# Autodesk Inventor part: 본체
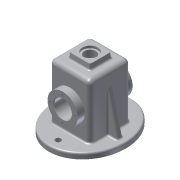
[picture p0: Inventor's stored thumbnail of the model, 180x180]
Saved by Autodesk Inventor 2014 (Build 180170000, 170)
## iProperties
Created: 2017-07
Part Number: 본체
Material: 알루미늄 6061
Document SubType Name: Modeling
Designer: user
Density: 2.71 g/cm^3
Appearance: 알루미늄 - 평지
Mass: 880.579 g
Surface Area: 992.163 cm^2
Volume: 324.937 cm^3
Author: user
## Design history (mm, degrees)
sketch "스케치1" dims "d0" = 75, "d1" = 65
  geometry: L1 (-99.161, 0)-(101.548, 0); C1 r 5 at (-58, 0); C2 r 5 at (58, 0); 2 further points; 1 other entity
  constraints: 3 point on line, 2 centre point, 2 end point, 1 coincident, 1 horizontal, 2 other
  dimensions: "d2" = 10 diameter of C1; "d3" = 10 diameter of C2; "d4" = 58 distance of point (0, 0) C2.centre; "d5" = 58 distance of point (0, 0) C1.centre
extrude "돌출1" new body sketch "스케치1" distance "d6" = 10; taper "d7" = 0 deg
sketch "스케치2"
  geometry: L1 (37, -37)-(-37, -37); L2 (-37, -37)-(-37, 37); L3 (-37, 37)-(37, 37); L4 (37, 37)-(37, -37); L5 (37, -37)-(-37, 37); L6 (-37, -37)-(37, 37); 1 further point
  constraints: 12 end point, 2 midpoint, 2 parallel, 1 horizontal, 1 perpendicular
  dimensions: "d8" = 74 distance of L2.end L3.end; "d9" = 74 distance of L1.end L2.end
extrude "돌출2" join sketch "스케치2" distance "d10" = 100; taper "d11" = 0 deg
sketch "스케치3"
  geometry: L1 (37, 10)-(-37, 10) reference; L2 (37, 10)-(37, 110) reference; L3 (-37, 110)-(37, 110) reference; L4 (-37, 10)-(-37, 110) reference; L5 (32, 105)-(32, 15); L6 (-32, 15)-(-32, 105); L7 (-32, 105)-(32, 105); L8 (32, 15)-(32, 0); L9 (-32, 15)-(-32, 0); L10 (-32, 0)-(32, 0); 1 further point
  constraints: 12 end point, 2 perpendicular, 1 parallel, 1 other
  dimensions: "d12" = 5 distance between parallel lines of L4 L6
extrude "돌출3" cut sketch "스케치3" stored distance "d13" = 64; taper "d14" = 0 deg
sketch "스케치6"
  geometry: L1 (0, 74)-(100, 74) reference; L2 (100, 74)-(100, 0) reference; L3 (-10, 102)-(-10, -28) reference; C1 r 27.5 at (45, 37); C2 r 16 at (45, 37); 1 further point
  constraints: 2 centre point, 1 coincident
  dimensions: "d25" = 55 diameter of C1; "d26" = 32 diameter of C2; "d27" = 37 distance from line of L1 C2.centre; "d29" = 55 distance from line of L3 C1.centre
extrude "돌출5" join sketch "스케치6" distance "d30" = 13; taper "d31" = 0 deg
sketch "스케치7"
  geometry: L1 (37, 10)-(37, 110) reference; L2 (65, 10)-(-65, 10) reference; L3 (65, 10)-(-65, 10) reference; L4 (-65, 0)-(65, 0) reference; L5 (65, 10)-(65, 0); L6 (55, 10)-(37, 82.194); 1 further point
  constraints: 4 end point, 2 point on line, 1 perpendicular
  dimensions: "d32" = 10 distance from line of L5 L6.start; "d33" = 14 deg angle of L5 L6
feature "리브1" sketch "스케치7" dims "d34" = 1, "d35" = 10, "d36" = 0, "d37" = 0, "d38" = 1, "d39" = 1
sketch "스케치8"
  geometry: L1 (-20, -20)-(20, -20); L2 (20, -20)-(20, 20); L3 (20, 20)-(-20, 20); L4 (-20, 20)-(-20, -20); L5 (-20, -20)-(20, 20); L6 (20, -20)-(-20, 20); 1 further point
  constraints: 12 end point, 2 midpoint, 2 parallel, 1 horizontal, 1 perpendicular
  dimensions: "d41" = 40 distance of L3.end L2.end; "d42" = 40 distance of L2.end L1.end
extrude "돌출6" join sketch "스케치8" distance "d44" = 10; taper "d45" = -5 deg
sketch "스케치9"
  geometry: C1 r 10.5 at (0, 0); C2 r 14 at (0, 0); 1 further point
  constraints: 2 centre point, 2 coincident
  dimensions: "d46" = 21 diameter of C1; "d47" = 28 diameter of C2
extrude "돌출7" cut sketch "스케치9" stored distance "d48" = 10; taper "d49" = 0 deg
extrude "돌출8" cut sketch "스케치9" distance "d50" = 4; taper "d51" = 0 deg
sketch "스케치10"
  geometry: L1 (32, 0)-(32, 105) reference; L2 (-32, 105)-(-32, 0) reference; L3 (76.395, 55)-(-68.157, 55); L4 (0, -17.114)-(0, 133.435); L5 (-37, 110)-(37, 110) reference; L6 (32, 82.5)-(25.146, 75.646); L7 (25, 75.293)-(25, 55); L8 (32, 82.5)-(32, 55); L9 (25, 55)-(32, 55); L10 (-32, 82.5)-(-25, 75.5); L11 (-25, 75.5)-(-25, 55); L12 (-32, 82.5)-(-32, 55); L13 (-25, 55)-(-32, 55); A1 r 0.5 centre (25.5, 75.293) between (25.146, 75.646) and (25, 75.293); 2 further points
  constraints: 20 end point, 11 point on line, 5 perpendicular, 3 symmetric about line, 2 point on circle, 2 tangent, 1 centre point
  dimensions: "d52" = 55 distance between parallel lines of L5 L3; "d53" = 7 distance between parallel lines of L1 L7; "d54" = 135 deg angle of L1 L6; "d55" = 55 diameter of L6.start L3; "d72" = 0.5 radius of A1
revolve "회전1" sketch "스케치10" stored, may be unused: angle "d60" = 90 deg
sketch "스케치11"
  geometry: C1 r 16 at (0, 0) reference; C2 r 27.5 at (0, 0) reference; C3 r 16 at (0, 0); 1 further point
  constraints: 1 centre point, 1 coincident
  dimensions: "d61" = 32 diameter of C3
extrude "돌출9" cut sketch "스케치11" stored distance "d62" = 4; taper "d63" = 0 deg
sketch "스케치12"
  geometry: C1 r 16 at (0, 0) reference; C2 r 27.5 at (0, 0) reference; A1 r 22.5 centre (0, 0) between (22.5, 0) and (0, 22.5); 3 further points
  constraints: 4 point on circle, 1 centre point, 1 coincident
  dimensions: "d64" = 45 diameter of A1
hole "구멍1" sketch "스케치12" at (22.5, 0), (0, 22.5), (0, -22.5), (-22.5, 0) diameter "d65" = 3.242; stored, may be unused: countersink angle "d69" = 90 deg, drill point angle "d71" = 118 deg; dims "d66" = 8, "d67" = 4, "d68" = 2, "d70" = 10
fillet "모깎기1" dims "d73" = 8
fillet "모깎기2" dims "d74" = 8
fillet "모깎기3" dims "d75" = 3
fillet "모깎기4" dims "d76" = 3
fillet "모깎기5" dims "d77" = 3
fillet "모깎기6" dims "d78" = 3
fillet "모깎기7" dims "d79" = 3
fillet "모깎기8" dims "d80" = 3
fillet "모깎기9" dims "d81" = 3
fillet "모깎기10" dims "d82" = 3
chamfer "모따기1" distance "d83" = 1; stored, may be unused: second distance "d84" = 2, angle "d85" = 45 deg
fillet "모깎기11" dims "d86" = 0.5
fillet "모깎기12" dims "d87" = 0.5
fillet "모깎기13" dims "d88" = 0.5
node "작업 평면1"
sketch "스케치13"
  geometry: L1 (0, -8)-(89, -8) reference; L2 (-18, 45.137)-(-18, 12.863) reference; 3 further points
  constraints: 1 coincident, 1 other
  dimensions: "d90" = 30 distance from line of L2 point (12, 29); "d91" = 37 distance from line of L1 point (12, 29)
feature "엠보싱1" sketch "스케치13" dims "d0" = 75, "d1" = 65, "d2" = 10, "d3" = 10, "d4" = 58, "d5" = 58, "d92" = 0.5, "d93" = 0
fillet "모깎기14" dims "d94" = 3
fillet "모깎기15" dims "d95" = 3
node "솔리드1"
mirror "대칭2"
mirror "대칭3"
mirror "대칭4"
node "투영된 루프1"
node "투영된 루프4"
node "투영된 루프5"
node "투영된 루프6"
other parameters: "d89" = 162.25
